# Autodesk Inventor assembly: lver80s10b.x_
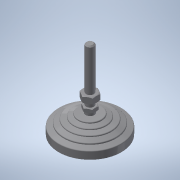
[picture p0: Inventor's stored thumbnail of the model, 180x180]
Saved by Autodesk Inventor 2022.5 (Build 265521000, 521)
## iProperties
Part Number: lver80s10b.x_
Material: 一般
Document SubType Name: Assembly
Designer: ImaoCorp
Sending System: SOLIDWORKS 2017-2017317
MC: AMD64
MC_MODEL: Intel64 Family 6 Model 60 Stepping 3, GenuineIntel
OS: Windows_NT
FRU: Parasolid Version 29.0, build 201,  4-17-2017
FORMAT: text
GUISE: transmit
KEY: lver80s10b
FILE: lver80s10b.x_t
DATE: Mon Jul 01 18:28:07 2019
Author: ImaoCorp
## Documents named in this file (3)
- X:\14_SW2022-Inv2022\00_全2023-1023新製品(TCC)まで\l\lver80s10b\LVER80S10B.iam
- X:\14_SW2022-Inv2022\00_全2023-1023新製品(TCC)まで\l\lver80s10b\lver80s10b_01.ipt
- X:\14_SW2022-Inv2022\00_全2023-1023新製品(TCC)まで\l\lver80s10b\lver80s10b_02.ipt
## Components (2 placed, 2 different names)
1. lver80s10b_01
2. lver80s10b_02
